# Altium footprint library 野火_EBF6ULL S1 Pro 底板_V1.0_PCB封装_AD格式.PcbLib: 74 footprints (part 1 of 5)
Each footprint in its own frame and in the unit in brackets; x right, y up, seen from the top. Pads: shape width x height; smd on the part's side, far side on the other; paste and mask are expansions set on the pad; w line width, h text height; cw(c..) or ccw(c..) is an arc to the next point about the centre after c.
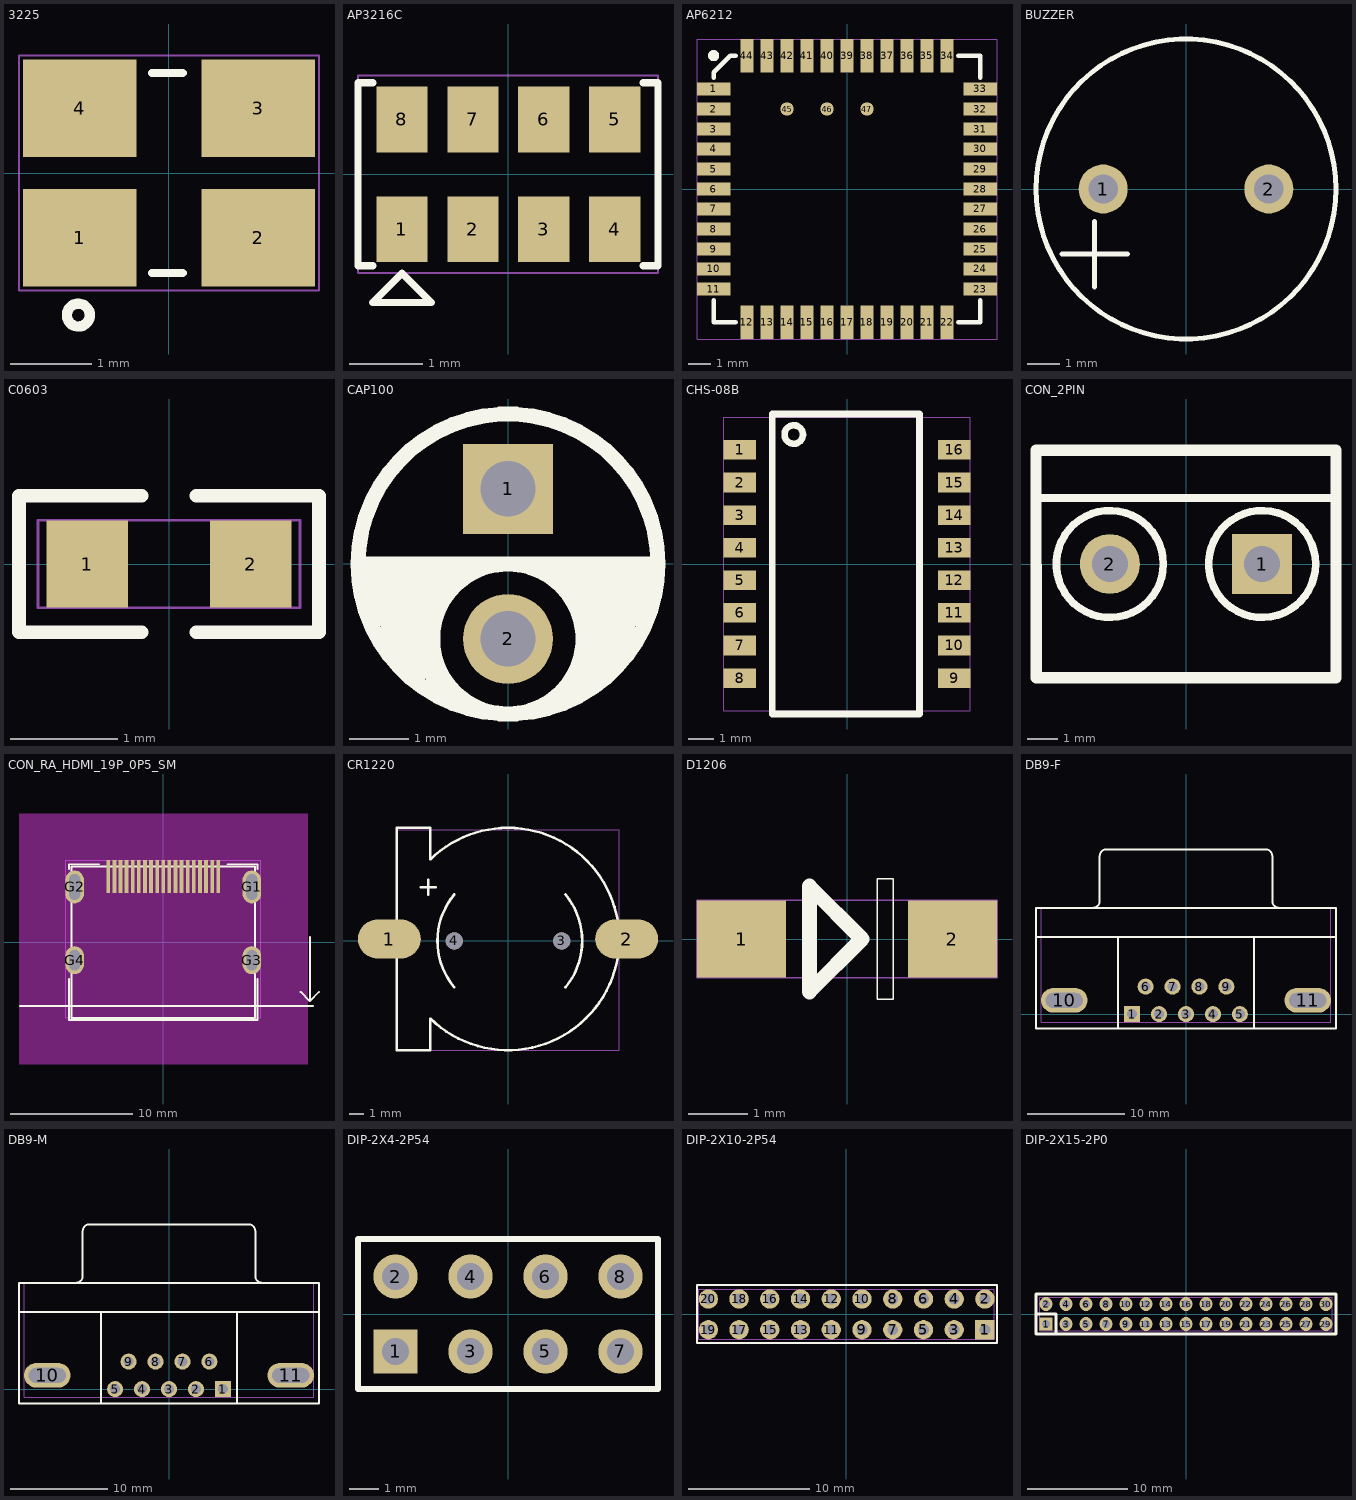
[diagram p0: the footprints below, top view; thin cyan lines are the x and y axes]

## 3225 [mil]
pads (4):
  rect 55.12x47.24 smd mask+1.97: 1(-43.3,-31.5) 2(43.31,-31.5) 3(43.31,31.49) 4(-43.3,31.49)
Top Overlay:
  circle w5: c-44,-69 r5.57
  lines w3.94: -8.3,-48.51 6.7,-48.51 ; -8.3,48.51 6.7,48.51
Top Assembly:
  text "Y2" at -38.93,-25 h50
Mechanical 20:
  lines w1: -72.83,-57.09 -72.83,57.08 72.84,57.08 72.84,-57.09 -72.83,-57.09

## AP3216C [mil]
pads (8):
  rect 27.56x35.43 smd mask+0.98: 1(-57.28,-29.53) 2(-19.09,-29.53) 3(19.09,-29.53) 4(57.28,-29.53) 5(57.28,29.53) 6(19.09,29.53) 7(-19.09,29.53) 8(-57.28,29.53)
Top Overlay:
  lines w3.94: -73.03,-49.21 -80.91,-49.21 -80.91,49.21 -73.03,49.21 ; 72.64,-49.21 80.51,-49.21 80.51,49.21 72.64,49.21 ; -73.03,-68.9 -41.54,-68.9 -57.28,-53.15 -73.03,-68.9
Top Assembly:
  text "U15" at 58.56,25 h50
Mechanical 20:
  lines w1: -80.91,-53.15 80.51,-53.15 80.51,53.15 -80.91,53.15 -80.91,-53.15

## AP6212 [mm]
pads (47):
  rect 1.5x0.6 smd mask+0.05: 1(-6,4.5) 2(-6,3.6) 3(-6,2.7) 4(-6,1.8) 5(-6,0.9) 6(-6,0) 7(-6,-0.9) 8(-6,-1.8) 9(-6,-2.7) 10(-6,-3.6) 11(-6,-4.5) 23(6,-4.5) 24(6,-3.6) 25(6,-2.7) 26(6,-1.8) 27(6,-0.9) 28(6,0) 29(6,0.9) 30(6,1.8) 31(6,2.7) 32(6,3.6) 33(6,4.5)
  rect 0.6x1.5 smd mask+0.05: 12(-4.5,-6) 13(-3.6,-6) 14(-2.7,-6) 15(-1.8,-6) 16(-0.9,-6) 17(0,-6) 18(0.9,-6) 19(1.8,-6) 20(2.7,-6) 21(3.6,-6) 22(4.5,-6) 34(4.5,6) 35(3.6,6) 36(2.7,6) 37(1.8,6) 38(0.9,6) 39(0,6) 40(-0.9,6) 41(-1.8,6) 42(-2.7,6) 43(-3.6,6) 44(-4.5,6)
  round 0.6 smd mask+0.05: 45(-2.7,3.6) 46(-0.9,3.6) 47(0.9,3.6)
Top Overlay:
  circle w0.25: c-6,6 r0.125
  lines w0.2: -6,-5 -6,-6 -5,-6 ; -6,5 -6,5.25 -5.25,6 -5,6 ; 5,-6 6,-6 6,-5 ; 5,6 6,6 6,5
Top Assembly:
  text "U5" at 1.022,0.635 h1.27
Mechanical 20:
  lines w0.025: -6.75,-6.75 6.75,-6.75 6.75,6.75 -6.75,6.75 -6.75,-6.75

## BUZZER [mil]
pads (2):
  round 59.06 hole 35.43 mask+2: 1(-100,0) 2(100,0)
Top Overlay:
  circle w6: c0,0 r181.1
  lines w6: -149.61,-78.74 -70.87,-78.74 ; -110.24,-118.11 -110.24,-39.37
Top Assembly:
  text "PZ1" at 50.47,25 h50
Mechanical 20:
  circle w1: c0,0 r181.1

## C0603 [mil]
pads (2):
  rect 30x32 smd mask+2.5: 1(-30,0) 2(30,0)
Top Overlay:
  lines w5: -10,-25 -55,-25 -55,25 -10,25 ; 10,-25 55,-25 55,25 10,25
Top Assembly:
  text "C99" at -62.61,-25 h50
Mechanical 20:
  lines w1: -48,-16 -48,16 48,16 48,-16 -48,-16

## CAP100 [mil]
pads (2):
  rect 60x60 hole 37 mask+2: 1(0,50)
  round 60 hole 37 mask+2: 2(0,-50)
Top Overlay:
  circle w10: c0,0 r100
  lines w10: -100,0 100,0 ; -90,-40 -90,0 ; -80,-60 -80,-5 ; -70,-70 -70,-5 ; -60,-75 -60,-5 ; -50,-85 -50,0 ; -45,-85 -45,-80 ; -40,-20 -40,0 ; -30,-10 -30,0 ; 35,-10 35,-5 ; 40,-20 40,-5 ; 45,-85 45,-80 ; 50,-85 50,-5 ; 60,-80 60,-5 ; 70,-70 70,-5 ; 80,-60 80,-5 ; 90,-40 90,-5 ; 0,-100 cw(c-0.26,-50) 0,0 cw(c0,-50) 0,-100
Top Assembly:
  text "C97" at -63.8,-25 h50
Mechanical 20:
  circle w1: c0,0 r100

## CHS-08B [mil]
pads (16):
  rect 50x30 smd mask+2.5: 1(-164.37,175) 2(-164.37,125) 3(-164.37,75) 4(-164.37,25) 5(-164.37,-25) 6(-164.37,-75) 7(-164.37,-125) 8(-164.37,-175) 9(164.37,-175) 10(164.37,-125) 11(164.37,-75) 12(164.37,-25) 13(164.37,25) 14(164.37,75) 15(164.37,125) 16(164.37,175)
Top Overlay:
  circle w10: c-81.69,198.62 r14.19
  lines w10: -114.37,-230.12 -114.37,230.12 111.22,230.12 111.22,-230.12 -114.37,-230.12
Top Assembly:
  text "SW5" at -67.73,-25 h50
Mechanical 20:
  lines w1: -189.37,-225 -189.37,225 189.37,225 189.37,-225 -189.37,-225

## CON_2PIN [mm]
pads (2):
  rect 2x2 hole 1.2 mask+0.051: 1(2.54,0)
  round 2 hole 1.2 mask+0.051: 2(-2.54,0)
Top Overlay:
  circle w0.254: c-2.54,0 r1.783
  circle w0.254: c2.54,0 r1.783
  lines w0.254: -5.004,2.2 5.004,2.2
  lines w0.381: -5.004,3.8 -5,-3.8 5.004,-3.8 5.004,3.8 -5.004,3.8
Top Assembly:
  text "J6" at -0.859,-0.635 h1.27
Mechanical 20:
  lines w0.025: -5.004,-3.8 5.004,-3.8 5.004,3.8 -5.004,3.8 -5.004,-3.8

## CON_RA_HDMI_19P_0P5_SM [mil]
height 249
pads (23):
  rect 12x106 smd mask+2: 1(177.17,211.61) 2(157.48,211.61) 3(137.8,211.61) 4(118.11,211.61) 5(98.43,211.61) 6(78.74,211.61) 7(59.06,211.61) 8(39.37,211.61) 9(19.69,211.61) 10(0,211.61) 11(-19.69,211.61) 12(-39.37,211.61) 13(-59.06,211.61) 14(-78.74,211.61) 15(-98.43,211.61) 16(-118.11,211.61) 17(-137.8,211.61) 18(-157.48,211.61) 19(-177.17,211.61)
  oval 59x106 hole 35 slot 83 at 90 deg mask+2: G1(285.43,178.15) G2(-285.43,178.15)
  oval 59x90 hole 35 slot 66 at 90 deg mask+2: G3(285.43,-58.07) G4(-285.43,-58.07)
Top Layer keep-out:
  region: -464.93,-394.09 -464.93,414.61 464.93,414.61 464.93,-394.09
Top Overlay:
  lines w6: -462.6,-205.71 285.43,-205.71 482.28,-205.71 ; -303.26,-118.11 -303.26,-251.09 303.26,-251.09 303.26,-118.11 ; -303.26,236.22 -303.26,251.09 -206.69,251.09 ; 206.69,251.09 303.26,251.09 303.26,236.22 ; 442.91,-160.43 472.44,-189.96 ; 472.44,16.73 472.44,-189.96 ; 501.97,-160.43 472.44,-189.96 ; -296.26,-244.09 -296.26,244.09 296.26,244.09 296.26,-244.09 -296.26,-244.09
Top Assembly:
  text "J1001" at -87.13,-25 h50
Mechanical 20:
  lines w1: -314.93,-244.09 -314.93,264.61 314.93,264.61 314.93,-244.09 -314.93,-244.09

## CR1220 [mil]
pads (4):
  oval 169.29x106.3 smd mask+1.97: 1(-320,5) 2(320,5)
  round 46 hole 46 unplated mask+2: 3(145,0) 4(-145,0)
Top Overlay:
  lines w7: -235,145 -195,145 ; -215,125 -215,165 ; -209.62,-209.61 -210,-295 -300,-295 -300,5 -300,305 -210,305 -209.62,219.61 ; -209.52,-209.7 ccw(c0,5) 298.19,-27.92 ; -209.52,219.71 cw(c0,5.01) 0,305 cw(c0,5) 298.19,37.92 ; -145.23,-124.72 cw(c5,0) -145.01,124.99 ; 155.01,-124.99 ccw(c5,0) 155.01,124.98
Top Assembly:
  text "CN3" at -65.11,-25 h50
Mechanical 20:
  lines w1: -300,-295 -300,300 300,300 300,-295 -300,-295

## D1206 [mil]
pads (2):
  rect 59.06x51.18 smd mask+2: 1(-70,0) 2(70,0)
Top Overlay:
  lines w1: 20,-40 20,40 30.75,40 30.75,-40 20,-40
  lines w10: -25,-35 10,0 -25,35 -25,-35
Top Assembly:
  text "D10" at -57.25,-25 h50
Mechanical 20:
  lines w1: -99.53,-25.59 99.53,-25.59 99.53,25.59 -99.53,25.59 -99.53,-25.59

## DB9-F [mil]
pads (11):
  rect 65x65 hole 40 mask+2: 1(-218.11,0)
  round 65 hole 40 mask+2: 2(-109.06,0) 3(0,0) 4(109.06,0) 5(218.11,0) 6(-163.58,111.81) 7(-54.53,111.81) 8(54.53,111.81) 9(163.58,111.81)
  oval 188x100 hole 60 slot 150 at 0 deg mask+2: 10(-491.93,55.91) 11(491.93,55.9)
Top Overlay:
  lines w7.87: -606.3,311.81 606.3,311.81 ; -376.38,430.12 ccw(c-376.38,457.48) -349.02,457.48 -348.82,638.78 cw(c-321.46,638.78) -321.46,666.14 321.46,666.14 cw(c321.46,638.78) 348.82,638.78 349.02,457.48 ccw(c376.38,457.48) 376.38,430.12 ; -275.59,-58.27 -275.59,311.81 ; 275.59,-58.27 275.59,311.81 ; -606.3,-58.27 606.3,-58.27 606.3,429.92 -606.3,429.92 -606.3,-58.27
Top Assembly:
  text "CON1" at -79.27,-25 h50
Mechanical 20:
  lines w1: -585.63,-32.5 585.63,-32.5 585.63,429.92 -585.63,429.92 -585.63,-32.5

## DB9-M [mil]
pads (11):
  rect 65x65 hole 40 mask+2: 1(218.11,0)
  round 65 hole 40 mask+2: 2(109.06,0) 3(0,0) 4(-109.06,0) 5(-218.11,0) 6(163.58,111.81) 7(54.53,111.81) 8(-54.53,111.81) 9(-163.58,111.81)
  oval 188x100 hole 60 slot 150 at 0 deg mask+2: 10(-491.93,55.91) 11(491.93,55.9)
Top Overlay:
  lines w7.87: -606.3,311.81 606.3,311.81 ; -376.38,430.12 ccw(c-376.38,457.48) -349.02,457.48 -348.82,638.78 cw(c-321.46,638.78) -321.46,666.14 321.46,666.14 cw(c321.46,638.78) 348.82,638.78 349.02,457.48 ccw(c376.38,457.48) 376.38,430.12 ; -275.59,-58.27 -275.59,311.81 ; 275.59,-58.27 275.59,311.81 ; -606.3,-58.27 606.3,-58.27 606.3,429.92 -606.3,429.92 -606.3,-58.27
Top Assembly:
  text "CON2" at -89.99,-25 h50
Mechanical 20:
  lines w1: -585.63,-32.5 585.63,-32.5 585.63,429.92 -585.63,429.92 -585.63,-32.5

## DIP-2X4-2P54 [mil]
pads (8):
  rect 59.06x59.06 hole 35.43 mask+2: 1(-150,-50)
  round 59.06 hole 35.43 mask+2: 2(-150,50) 3(-50,-50) 4(-50,50) 5(50,-50) 6(50,50) 7(150,-50) 8(150,50)
Top Overlay:
  lines w8.66: -189.37,100 -200,100 ; -200,100 200,100 200,-100 -200,-100 -200,100
Top Assembly:
  text "J8" at 35,25 h50
Mechanical 20:
  lines w1: -200,-100 -200,100 200,100 200,-100 -200,-100

## DIP-2X10-2P54 [mil]
pads (20):
  rect 62.99x62.99 hole 35.43 mask+2: 1(451.57,-50)
  round 62.99 hole 35.43 mask+2: 2(451.57,50) 3(351.57,-50) 4(351.57,50) 5(251.57,-50) 6(251.57,50) 7(151.57,-50) 8(151.57,50) 9(51.57,-50) 10(51.57,50) 11(-48.43,-50) 12(-48.43,50) 13(-148.43,-50) 14(-148.43,50) 15(-248.43,-50) 16(-248.43,50) 17(-348.43,-50) 18(-348.43,50) 19(-448.43,-50) 20(-448.43,50)
Top Overlay:
  lines w5.91: -485.43,-93.31 -485.43,95.67 490.94,95.67 490.94,-93.31 -485.43,-93.31
Top Assembly:
  text "J21" at 46.54,25 h50
Mechanical 20:
  lines w1: -479.92,-81.5 -479.92,81.49 481.5,81.49 481.5,-81.5 -479.92,-81.5

## DIP-2X15-2P0 [mil]
pads (30):
  rect 50x50 hole 32 mask+2: 1(-551.18,-39.37)
  oval 50x55 hole 32 mask+2: 2(-551.18,39.37) 3(-472.44,-39.37) 4(-472.44,39.37) 5(-393.7,-39.37) 6(-393.7,39.37) 7(-314.96,-39.37) 8(-314.96,39.37) 9(-236.22,-39.37) 10(-236.22,39.37) 11(-157.48,-39.37) 12(-157.48,39.37) 13(-78.74,-39.37) 14(-78.74,39.37) 15(0,-39.37) 16(0,39.37) 17(78.74,-39.37) 18(78.74,39.37) 19(157.48,-39.37) 20(157.48,39.37) 21(236.22,-39.37) 22(236.22,39.37) 23(314.96,-39.37) 24(314.96,39.37) 25(393.7,-39.37) 26(393.7,39.37) 27(472.44,-39.37) 28(472.44,39.37) 29(551.18,-39.37) 30(551.18,39.37)
Top Overlay:
  lines w10: -590.55,0 -511.81,0 -511.81,-78.74 ; -590.55,-78.74 590.55,-78.74 590.55,78.74 -590.55,78.74 -590.55,-78.74
Top Assembly:
  text "J38" at 57.25,25 h50
Mechanical 20:
  lines w1: -576.18,-66.87 576.18,-66.87 576.18,66.87 -576.18,66.87 -576.18,-66.87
